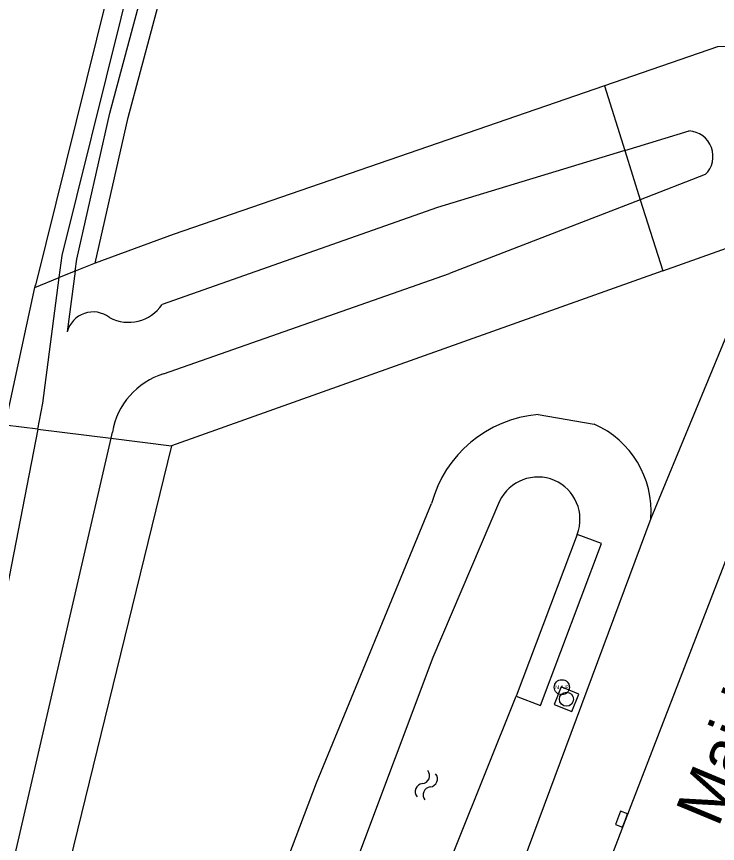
# Model space of a CAD drawing. Extents: x 131000 to 133013, y 393000 to 396501.
# Drawn here: x 131341.65 to 131378.89, y 393897.6 to 393941.51 of the extents above; entities that cross this region are included whole.
import ezdxf

# ---------------------------------------------------------------- set-up
doc = ezdxf.new("R2010")
doc.units = 0
for name, color, linetype in [('gg-anno-openbare ruimte label', 7, 'Continuous'), ('gg-knt-verharding', 7, 'Continuous'), ('gg-kntw-bovenkant insteek waterloop', 7, 'Continuous'), ('gg-kntw-waterlijn', 7, 'Continuous'), ('gg-kwrk-uitstroombak niveau min 01', 7, 'Continuous'), ('gt-grn-groengrens', 7, 'Continuous'), ('gt-symb-hoogtemerk', 7, 'Continuous'), ('gt-symb-kolk', 7, 'Continuous'), ('gt-symb-rioolschacht', 7, 'Continuous'), ('gt-symb-watersymbool', 7, 'Continuous'), ('gx-grn-maaiveld', 7, 'Continuous')]:
    doc.layers.add(name, color=color, linetype=linetype)

# ---------------------------------------------------------------- blocks, each defined once
blk = doc.blocks.new('gt0-KOLK')
at = {"layer": 'gt-symb-kolk'}
blk.add_lwpolyline([(0, 0), (0.375, 0), (0.375, 0.4), (-0.375, 0.4), (-0.375, 0), (0, 0)], dxfattribs=at)
blk = doc.blocks.new('gt0-WA')
at = {"layer": 'gt-symb-watersymbool'}
for centre, start, end in [((-0.323, 0.022), 28.0725, 151.9275), ((0.427, 0.422), 208.0725, 331.9275), ((-0.323, -0.428), 28.0725, 151.9275), ((0.427, -0.028), 208.0725, 331.9275)]:
    blk.add_arc(centre, 0.425, start, end, dxfattribs=at)
blk = doc.blocks.new('gt0-RS')
at = {"layer": 'gt-symb-rioolschacht'}
blk.add_lwpolyline([(-0.5, -0.5), (0.5, -0.5), (0.5, 0.5), (-0.5, 0.5)], close=True, dxfattribs=at)
blk.add_circle((0, 0), 0.375, dxfattribs=at)
blk = doc.blocks.new('gt0-HMERK')
at = {"layer": 'gt-symb-hoogtemerk'}
blk.add_circle((0, 0), 0.4, dxfattribs=at)
blk.add_text('N.A.P', height=0.2, dxfattribs=at).set_placement((-0.354, -0.1))

msp = doc.modelspace()

# ---------------------------------------------------------------- linework, layer by layer
at = {"layer": 'gg-knt-verharding'}
msp.add_lwpolyline([(131390.166, 393938.639), (131389.255, 393936.93), (131387.468, 393933.218), (131386.225, 393930.35), (131380.634, 393916.039), (131373.975, 393898.812), (131364.029, 393872.907), (131355.727, 393851.362)], dxfattribs=at)
at = {"layer": 'gg-kntw-bovenkant insteek waterloop'}
for p, q in [((131352.5, 393966.865), (131342.655, 393927.235)), ((131369.355, 393920.367), (131372.338, 393919.865))]:
    msp.add_line(p, q, dxfattribs=at)
for points in [[(131284.174, 393709.146), (131292.682, 393732.478), (131302.115, 393756.486), (131311.252, 393780.687), (131320.372, 393804.371), (131329.937, 393828.866), (131339.298, 393853.11), (131348.553, 393876.996), (131357.591, 393900.819), (131363.703, 393915.64)], [(131375.352, 393914.857), (131358.065, 393868.418), (131348.765, 393844.959), (131339.126, 393819.96), (131329.317, 393794.86), (131319.505, 393769.527), (131310.311, 393744.867), (131300.831, 393720.659), (131296.153, 393708.202)]]:
    msp.add_lwpolyline(points, dxfattribs=at)
for centre, radius, start, end in [((131379.543, 393933.374), 6.547, 31.511, 95.749), ((131369.884, 393913.992), 6.397, 94.745, 165.0692), ((131370.291, 393915.222), 5.074, 355.8762, 66.206)]:
    msp.add_arc(centre, radius, start, end, dxfattribs=at)
at = {"layer": 'gg-kntw-waterlijn'}
for p, q in [((131364.019, 393931.37), (131349.38, 393926.219)), ((131349.464, 393922.527), (131364.644, 393927.866))]:
    msp.add_line(p, q, dxfattribs=at)
for points in [[(131367.314, 393915.765), (131363.772, 393907.474), (131351.811, 393875.64), (131333.874, 393828.912), (131325.673, 393808.732), (131316.877, 393784.795), (131309.414, 393765.455), (131299.931, 393741.482), (131287.975, 393711.346)], [(131292.541, 393709.577), (131297.286, 393722.588), (131303.63, 393739.007), (131311.889, 393760.873), (131326.539, 393799.18), (131343.777, 393843.128), (131358.673, 393881.667), (131368.196, 393905.416)]]:
    msp.add_lwpolyline(points, dxfattribs=at)
for centre, radius, start, end in [((131377.305, 393934.084), 1.346, 313.893, 87.04), ((131347.603, 393927.404), 2.136, 241.5831, 326.3156), ((131345.72, 393924.396), 1.423, 52.4986, 165.3951), ((131350.619, 393918.764), 3.936, 107.0557, 170.0774), ((131369.342, 393914.812), 2.241, 338.92, 154.8307)]:
    msp.add_arc(centre, radius, start, end, dxfattribs=at)
at = {"layer": 'gg-kwrk-uitstroombak niveau min 01'}
msp.add_line((131371.433, 393914.006), (131368.196, 393905.416), dxfattribs=at)
msp.add_lwpolyline([(131368.196, 393905.416), (131369.481, 393904.93), (131372.735, 393913.525), (131371.433, 393914.006)], dxfattribs=at)
at = {"layer": 'gt-grn-groengrens'}
msp.add_line((131381.6, 393929.997), (131375.352, 393914.857), dxfattribs=at)
at = {"layer": 'gx-grn-maaiveld'}
for p, q in [((131378.887, 393939.888), (131372.887, 393937.823)), ((131372.887, 393937.823), (131373.965, 393934.393)), ((131373.965, 393934.393), (131377.375, 393935.429)), ((131373.965, 393934.393), (131364.019, 393931.37)), ((131373.965, 393934.393), (131374.786, 393931.781)), ((131378.239, 393933.114), (131374.786, 393931.781)), ((131374.786, 393931.781), (131364.644, 393927.866)), ((131374.786, 393931.781), (131375.976, 393927.995)), ((131375.976, 393927.995), (131381.6, 393929.997)), ((131345.825, 393928.406), (131344.765, 393927.981)), ((131342.631, 393927.126), (131343.925, 393927.645)), ((131344.765, 393927.981), (131343.925, 393927.645)), ((131344.765, 393927.981), (131344.343, 393924.755)), ((131375.976, 393927.995), (131349.884, 393918.707)), ((131342.631, 393927.126), (131342.655, 393927.235)), ((131341.041, 393919.814), (131342.631, 393927.126)), ((131342.783, 393919.596), (131341.041, 393919.814)), ((131342.783, 393919.596), (131346.664, 393919.11)), ((131346.741, 393919.442), (131346.664, 393919.11)), ((131346.664, 393919.11), (131337.605, 393879.926)), ((131346.664, 393919.11), (131349.884, 393918.707))]:
    msp.add_line(p, q, dxfattribs=at)
for points in [[(131344.765, 393927.981), (131344.85, 393928.628), (131346.616, 393936.382), (131348.588, 393943.771), (131358.785, 393978.853), (131363.735, 394000.226), (131364.884, 394005.754)], [(131343.925, 393927.645), (131344.079, 393928.82), (131353.476, 393966.647)], [(131345.825, 393928.406), (131347.587, 393936.142), (131349.548, 393943.492)], [(131372.887, 393937.823), (131349.965, 393929.936), (131345.825, 393928.406)], [(131342.783, 393919.596), (131343.053, 393920.98), (131343.925, 393927.645)], [(131342.783, 393919.596), (131336.599, 393887.862), (131335.215, 393880.389)], [(131349.884, 393918.707), (131343.014, 393890.656), (131340.746, 393879.318)]]:
    msp.add_lwpolyline(points, dxfattribs=at)

# ---------------------------------------------------------------- block references
at = {"layer": 'gt-symb-hoogtemerk'}
msp.add_blockref('gt0-HMERK', (131370.62, 393905.892), dxfattribs=at)
at = {"layer": 'gt-symb-kolk', "rotation": 68.95425918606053}
msp.add_blockref('gt0-KOLK', (131373.975, 393898.812), dxfattribs=at)
at = {"layer": 'gt-symb-rioolschacht', "rotation": -22.02484593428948}
msp.add_blockref('gt0-RS', (131370.866, 393905.254), dxfattribs=at)
at = {"layer": 'gt-symb-watersymbool', "rotation": -112.33338843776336}
msp.add_blockref('gt0-WA', (131363.445, 393900.733), dxfattribs=at)

# ---------------------------------------------------------------- texts
at = {"layer": 'gg-anno-openbare ruimte label'}
msp.add_text('Maidstone', height=2.5, rotation=67.4, dxfattribs=at).set_placement((131378.922, 393898.403))

doc.saveas('drawing.dxf')
